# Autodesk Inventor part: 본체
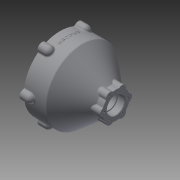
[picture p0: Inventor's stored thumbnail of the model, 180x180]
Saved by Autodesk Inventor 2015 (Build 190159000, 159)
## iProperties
Created: 2026-05
Part Number: 본체
Material: 일반
Document SubType Name: Modeling
Designer: 104
Density: 1 g/cm^3
Appearance: 기본값
Author: 104
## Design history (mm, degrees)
sketch "스케치2"
  geometry: C1 r 82 at (0, 0); 1 further point
  constraints: 1 centre point, 1 coincident
  dimensions: "d0" = 164 diameter of C1
extrude "돌출1" new body sketch "스케치2" distance "d1" = 50; taper "d2" = 0 deg
node "작업 평면1"
sketch "스케치3"
  geometry: C1 r 30.5 at (0, 0); 1 further point
  constraints: 1 centre point, 1 coincident
  dimensions: "d4" = 61 diameter of C1
extrude "돌출2" join sketch "스케치3" stored distance "d5" = 16; taper "d6" = 0 deg
node "작업 평면2"
sketch "스케치4"
  geometry: L1 (0, 82)-(0, -82) reference; L2 (0, -82)-(-50, -82) reference; L3 (-50, -82)-(-50, -30.5) reference; L4 (-50, -30.5)-(-126, -30.5) reference; L5 (-126, -30.5)-(-126, 30.5) reference; L6 (-126, 30.5)-(-50, 30.5) reference; L7 (-50, 30.5)-(-50, 82) reference; L8 (-50, 82)-(0, 82) reference; L9 (-50, 82)-(-111.375, 30.5); L10 (-50, 82)-(30.12, 82); L11 (61.344, 0)-(-157.224, 0) reference; 1 further point
  constraints: 4 end point, 1 equal length, 1 horizontal, 1 point on line
  dimensions: "d8" = 140 deg angle of L9 L10
revolve "회전1" sketch "스케치4" stored, may be unused: angle "d9" = 90 deg
sketch "스케치5"
  geometry: C1 r 82 at (0, 0) reference; C2 r 73 at (0, 0)
  constraints: 1 centre point, 1 coincident
  dimensions: "d10" = 146 diameter of C2
extrude "돌출3" cut sketch "스케치5" distance "d11" = 37; taper "d12" = 0 deg
sketch "스케치6"
  geometry: C1 r 73 at (0, 0) reference; C2 r 68 at (0, 0)
  constraints: 1 centre point, 1 coincident
  dimensions: "d13" = 136 diameter of C2
extrude "돌출4" cut sketch "스케치6" distance "d14" = 5; taper "d15" = 0 deg
sketch "스케치10"
  geometry: C1 r 30.5 at (0, 0) reference
hole "구멍1" sketch "스케치10" at (0, 0) diameter "d25" = 35; stored, may be unused: countersink angle "d29" = 82 deg, drill point angle "d31" = 0 deg; dims "d26" = 5.984, "d27" = 40, "d28" = 16, "d30" = 10.688
sketch "스케치12"
  geometry: C1 r 17.5 at (0, 0) reference; C2 r 68 at (0, 0) reference; C3 r 56 at (0, 0)
  constraints: 1 centre point, 1 coincident
  dimensions: "d32" = 112 diameter of C3
extrude "돌출8" cut sketch "스케치12" distance "d33" = 20; taper "d34" = 0 deg
sketch "스케치13"
  geometry: C1 r 17.5 at (0, 0) reference; C2 r 56 at (0, 0) reference; C3 r 40 at (0, 0)
  constraints: 1 centre point, 1 coincident
  dimensions: "d35" = 80 diameter of C3
extrude "돌출9" cut sketch "스케치13" distance "d36" = 16; taper "d37" = 0 deg
sketch "스케치14"
  geometry: C1 r 17.5 at (0, 0) reference; C2 r 40 at (0, 0) reference; C3 r 37 at (0, 0)
  constraints: 1 centre point, 1 coincident
  dimensions: "d38" = 74 diameter of C3
extrude "돌출10" cut sketch "스케치14" distance "d39" = 4; taper "d40" = 0 deg
sketch "스케치15"
  geometry: C1 r 17.5 at (0, 0) reference; C2 r 30.5 at (0, 0) reference; C3 r 20 at (0, 0)
  constraints: 1 centre point, 1 coincident
  dimensions: "d41" = 40 diameter of C3
extrude "돌출11" cut sketch "스케치15" distance "d42" = 12; taper "d43" = 0 deg
sketch "스케치16"
  geometry: L1 (0, 27)-(23.383, 13.5); L2 (23.383, 13.5)-(23.383, -13.5); L3 (23.383, -13.5)-(0, -27); L4 (0, -27)-(-23.383, -13.5); L5 (-23.383, -13.5)-(-23.383, 13.5); L6 (-23.383, 13.5)-(0, 27); A1 r 20 centre (0, 0) between (-14.391, -13.889) and (-19.224, -5.519) reference; A2 r 9 centre (-23.383, -13.5) between (-19.224, -5.519) and (-14.391, -13.889); 1 further point
  constraints: 12 end point, 4 point on circle, 1 centre point, 1 coincident, 13 other
  dimensions: "d45" = 18 diameter of A2
extrude "돌출12" join sketch "스케치16" stored distance "d46" = 0; taper "d47" = 0 deg
sketch "스케치17"
  geometry: A1 r 9 centre (0, -27) between (-8.72, -29.227) and (8.72, -29.227) reference; A2 r 9 centre (23.383, -13.5) between (20.951, -22.165) and (29.671, -7.062) reference; A3 r 9 centre (23.383, 13.5) between (29.671, 7.062) and (20.951, 22.165) reference; A4 r 9 centre (0, 27) between (8.72, 29.227) and (-8.72, 29.227) reference; A5 r 9 centre (-23.383, 13.5) between (-20.951, 22.165) and (-29.671, 7.062) reference; A6 r 9 centre (-23.383, -13.5) between (-29.671, -7.062) and (-20.951, -22.165) reference
hole "구멍2" sketch "스케치17" at (-23.383, 13.5), (0, 27), (23.383, 13.5), (23.383, -13.5), (0, -27), (-23.383, -13.5) diameter "d51" = 3.242; stored, may be unused: countersink angle "d55" = 82 deg, drill point angle "d57" = 118 deg; dims "d52" = 8, "d53" = 40, "d54" = 16, "d56" = 10
node "작업 평면3"
sketch "스케치18"
  geometry: L1 (0, -82)-(-71.014, -41); L2 (-71.014, -41)-(-71.014, 41); L3 (-71.014, 41)-(0, 82); L4 (0, 82)-(71.014, 41); L5 (71.014, 41)-(71.014, -41); L6 (71.014, -41)-(0, -82); A1 r 10 centre (71.014, 41) between (71.014, 31) and (62.354, 46); 3 further points
  constraints: 12 end point, 2 point on circle, 2 point on line, 1 centre point, 1 coincident, 1 vertical alignment, 14 other
  dimensions: "d60" = 20 diameter of A1
extrude "돌출13" join sketch "스케치18" distance "d61" = 15; taper "d62" = 0 deg
sketch "스케치19"
  geometry: C1 r 10 at (-71.014, 41); A1 r 82 centre (0, 0) between (-65.495, 49.339) and (-75.477, 32.051) reference; A2 r 10 centre (-71.014, 41) between (-65.495, 49.339) and (-75.477, 32.051) reference
  constraints: 1 centre point, 1 coincident, 1 concentric
extrude "돌출14" join sketch "스케치19" distance "d63" = 10; taper "d64" = 0 deg
fillet "모깎기1" dims "d65" = 10
sketch "스케치20"
  geometry: A1 r 10 centre (71.014, 41) between (75.477, 32.051) and (65.495, 49.339) reference; A2 r 10 centre (0, 82) between (9.981, 81.39) and (-9.981, 81.39) reference; A3 r 10 centre (-71.014, 41) between (-65.495, 49.339) and (-75.477, 32.051) reference; A4 r 10 centre (-71.014, -41) between (-75.477, -32.051) and (-65.495, -49.339) reference; A5 r 10 centre (0, -82) between (-9.981, -81.39) and (9.981, -81.39) reference; A6 r 10 centre (71.014, -41) between (65.495, -49.339) and (75.477, -32.051) reference
hole "구멍3" sketch "스케치20" at (0, -82), (-71.014, -41), (-71.014, 41), (0, 82), (71.014, 41), (71.014, -41) diameter "d69" = 4.917; stored, may be unused: countersink angle "d73" = 82 deg, drill point angle "d75" = 118 deg; dims "d70" = 12, "d71" = 40, "d72" = 16, "d74" = 14
sketch "스케치21"
  geometry: L1 (0, 62)-(53.694, 31); L2 (53.694, 31)-(53.694, -31); L3 (53.694, -31)-(0, -62); L4 (0, -62)-(-53.694, -31); L5 (-53.694, -31)-(-53.694, 31); L6 (-53.694, 31)-(0, 62); 1 further point
  constraints: 12 end point, 13 other
hole "구멍4" sketch "스케치21" at (0, 62), (53.694, 31), (53.694, -31), (0, -62), (-53.694, -31), (-53.694, 31) diameter "d77" = 3.242; stored, may be unused: countersink angle "d81" = 82 deg, drill point angle "d83" = 118 deg; dims "d78" = 8, "d79" = 40, "d80" = 16, "d82" = 10
fillet "모깎기2" dims "d84" = 0.6
fillet "모깎기3" dims "d85" = 1
chamfer "모따기1" distance "d86" = 1; stored, may be unused: second distance "d87" = 2, angle "d88" = 45 deg
fillet "모깎기4" dims "d89" = 3
chamfer "모따기2" distance "d90" = 1; stored, may be unused: second distance "d91" = 2, angle "d92" = 45 deg
fillet "모깎기5" dims "d93" = 3
chamfer "모따기3" distance "d94" = 1; stored, may be unused: second distance "d95" = 2, angle "d96" = 45 deg
chamfer "모따기4" distance "d97" = 1; stored, may be unused: second distance "d98" = 2, angle "d99" = 45 deg
fillet "모깎기6" dims "d100" = 3
chamfer "모따기5" distance "d101" = 1; stored, may be unused: second distance "d102" = 2, angle "d103" = 45 deg
fillet "모깎기7" dims "d104" = 3
fillet "모깎기8" dims "d105" = 3
fillet "모깎기9" dims "d106" = 3
node "작업 평면4"
sketch "스케치22"
  geometry: L1 (0, 29.801)-(0, -29.801) reference; 3 further points
  constraints: 1 horizontal alignment, 1 midpoint, 1 other
  dimensions: "d107" = 20 distance from line of L1 point (20, 0)
feature "엠보싱1" sketch "스케치22" dims "d108" = 0.5, "d109" = 0
node "솔리드1"
pattern_circular "원형 패턴1" dims angle "d49" = 360 deg
pattern_circular "원형 패턴2" dims "d67" = 360 deg
node "절단 모서리 투영1"
other parameters: "d3" = -126, "d7" = 0, "d58" = 0
